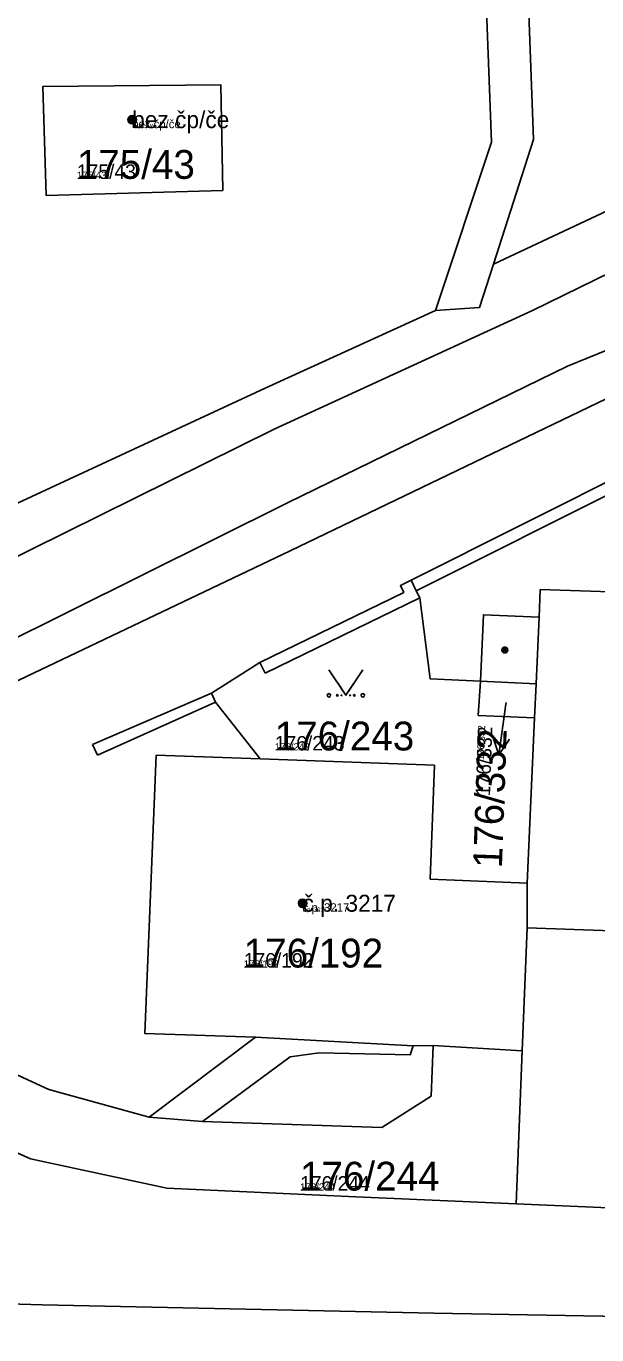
# Model space of a CAD drawing. Extents: x -759873 to -758487, y -975024 to -973516.
# Drawn here: x -759384.3 to -759350.6, y -974781.5 to -974704.3 of the extents above; entities that cross this region are included whole.
import ezdxf

# ---------------------------------------------------------------- set-up
doc = ezdxf.new("R2010")
doc.units = 0
for name, color, linetype in [('KAT_02_hranice parcel', 7, 'Continuous'), ('KAT_03_1000_st čísla parcelní', 7, 'Continuous'), ('KAT_03_1000_čísla parcelní', 7, 'Continuous'), ('KAT_03_1000_čísla popisná', 7, 'Continuous'), ('KAT_03_250_st čísla parcelní', 7, 'Continuous'), ('KAT_03_250_čísla parcelní', 7, 'Continuous'), ('KAT_03_250_čísla popisná', 7, 'Continuous'), ('KAT_03_500_st čísla parcelní', 7, 'Continuous'), ('KAT_03_500_čísla parcelní', 7, 'Continuous'), ('KAT_03_500_čísla popisná', 7, 'Continuous'), ('KAT_04_vnitřní kresba', 7, 'Continuous'), ('KAT_05_1000_značky kultur', 7, 'Continuous'), ('KAT_05_250_značky kultur', 7, 'Continuous'), ('KAT_05_500_značky kultur', 7, 'Continuous'), ('KAT_07_1000_značky budov', 7, 'Continuous'), ('KAT_07_250_značky budov', 7, 'Continuous'), ('KAT_07_500_značky budov', 7, 'Continuous'), ('KAT_12_pomocná šipka', 7, 'Continuous'), ('KAT_14_plocha_budovy', 7, 'Continuous'), ('KAT_14_plocha_pozemek', 7, 'Continuous')]:
    doc.layers.add(name, color=color, linetype=linetype)

msp = doc.modelspace()

# ---------------------------------------------------------------- linework, layer by layer
at = {"layer": 'KAT_02_hranice parcel'}
for p, q in [((-759354.3, -974745.08), (-759354.73, -974754.83)), ((-759354.74, -974757.45), (-759354.73, -974754.83)), ((-759355.03, -974764.72), (-759354.74, -974757.45)), ((-759355.03, -974764.72), (-759355.39, -974773.73))]:
    msp.add_line(p, q, dxfattribs=at)
for points in [[(-759360.14, -974721.06), (-759356.84, -974711.13), (-759357.26, -974700.21), (-759357.47, -974694.62)], [(-759318.71, -974700.17), (-759354.98, -974694.48), (-759354.76, -974700.34), (-759354.37, -974710.98), (-759356.72, -974718.32)], [(-759318.71, -974700.17), (-759321.9, -974701.95), (-759356.72, -974718.32)], [(-759372.67, -974713.98), (-759372.79, -974707.75), (-759383.27, -974707.85), (-759383.08, -974714.28), (-759372.67, -974713.98)], [(-759356.72, -974718.32), (-759357.54, -974720.88), (-759360.14, -974721.06)], [(-759338.69, -974720.79), (-759368.71, -974735.24), (-759393.08, -974746.85), (-759424.93, -974762.5)], [(-759407.29, -974742.88), (-759370.17, -974725.64), (-759360.14, -974721.06)], [(-759361.58, -974736.96), (-759348.29, -974730.29), (-759349.19, -974728.08), (-759348.55, -974727.8), (-759346.93, -974727.1), (-759346.28, -974726.82), (-759345, -974729.6), (-759333.48, -974730.01), (-759330.21, -974730.19), (-759329.89, -974726.69), (-759329.3, -974726.82)], [(-759370.47, -974747.49), (-759373.1, -974744.16), (-759373.34, -974743.62), (-759370.49, -974741.82), (-759362.01, -974737.68), (-759362.21, -974737.28), (-759361.58, -974736.96)], [(-759361.58, -974736.96), (-759361.27, -974737.59), (-759361.07, -974738), (-759360.45, -974742.78), (-759357.49, -974742.92)], [(-759323.14, -974738.53), (-759353.97, -974737.52), (-759354.04, -974739.15), (-759357.32, -974739), (-759357.49, -974742.92)], [(-759354.3, -974745.08), (-759357.62, -974744.93), (-759357.49, -974742.92)], [(-759357.49, -974742.92), (-759354.21, -974743.08), (-759354.3, -974745.08)], [(-759370.47, -974747.49), (-759376.59, -974747.27), (-759377.26, -974763.69), (-759370.74, -974763.9), (-759377.01, -974768.63)], [(-759354.73, -974754.83), (-759360.45, -974754.58), (-759360.2, -974747.87), (-759370.47, -974747.49)], [(-759354.74, -974757.45), (-759349.74, -974757.64), (-759349.83, -974759.39), (-759331.3, -974760.1), (-759331.26, -974758.35), (-759323.94, -974758.63), (-759321.81, -974758.71)], [(-759321.81, -974758.71), (-759321.95, -974763.67), (-759319.84, -974763.72), (-759319.94, -974767.65), (-759322.08, -974767.68), (-759322.29, -974775.16), (-759345.4, -974774.17), (-759355.39, -974773.73)], [(-759395.83, -974765.08), (-759394.67, -974760.92), (-759389.25, -974764.08), (-759382.92, -974767), (-759377.01, -974768.63)], [(-759424.93, -974762.5), (-759425.59, -974765.85), (-759424.23, -974769.73), (-759420.74, -974774.82), (-759416.74, -974776.65), (-759408.58, -974778.44), (-759401.14, -974779.15), (-759383.31, -974779.68), (-759360.24, -974780.18), (-759335.92, -974780.61), (-759318.75, -974781.06), (-759302.75, -974781.4)], [(-759377.01, -974768.63), (-759373.86, -974768.88), (-759368.7, -974765.06), (-759366.99, -974764.83), (-759361.64, -974764.95), (-759361.45, -974764.42), (-759360.28, -974764.39), (-759355.03, -974764.72)], [(-759355.39, -974773.73), (-759364.83, -974773.31), (-759375.96, -974772.8), (-759384.01, -974771.08), (-759388.88, -974768.9)]]:
    msp.add_lwpolyline(points, dxfattribs=at)
at = {"layer": 'KAT_03_1000_čísla popisná'}
for centre in [(-759378.01, -974709.81), (-759367.97, -974756.01)]:
    msp.add_circle(centre, 0.25, dxfattribs=at)
at = {"layer": 'KAT_03_250_čísla popisná'}
for centre in [(-759378.01, -974709.81), (-759367.97, -974756.01)]:
    msp.add_circle(centre, 0.0625, dxfattribs=at)
at = {"layer": 'KAT_03_500_čísla popisná'}
for centre in [(-759378.01, -974709.81), (-759367.97, -974756.01)]:
    msp.add_circle(centre, 0.125, dxfattribs=at)
at = {"layer": 'KAT_04_vnitřní kresba'}
for p, q in [((-759354.42, -974721.07), (-759327.47, -974707.8)), ((-759369.64, -974728.06), (-759354.42, -974721.07)), ((-759352.37, -974724.34), (-759343.54, -974720.75)), ((-759368.86, -974732.4), (-759352.37, -974724.34)), ((-759396.05, -974741.14), (-759369.64, -974728.06)), ((-759361.27, -974737.59), (-759347.98, -974730.92)), ((-759393.91, -974744.86), (-759368.86, -974732.4)), ((-759370.18, -974742.45), (-759361.07, -974738)), ((-759354.21, -974743.08), (-759354.04, -974739.15)), ((-759370.49, -974741.82), (-759370.18, -974742.45)), ((-759380.34, -974746.65), (-759373.34, -974743.62)), ((-759380.05, -974747.28), (-759373.1, -974744.16)), ((-759380.34, -974746.65), (-759380.05, -974747.28)), ((-759370.74, -974763.9), (-759361.45, -974764.42)), ((-759360.4, -974767.39), (-759360.28, -974764.39)), ((-759363.3, -974769.23), (-759360.4, -974767.39)), ((-759373.86, -974768.88), (-759363.3, -974769.23))]:
    msp.add_line(p, q, dxfattribs=at)
at = {"layer": 'KAT_05_1000_značky kultur'}
msp.add_lwpolyline([(-759366.42, -974742.249), (-759365.42, -974743.75), (-759364.42, -974742.249)], dxfattribs=at)
for centre in [(-759366.42, -974743.749), (-759364.42, -974743.749)]:
    msp.add_circle(centre, 0.1, dxfattribs=at)
at = {"layer": 'KAT_05_250_značky kultur'}
msp.add_lwpolyline([(-759365.67, -974743.375), (-759365.42, -974743.75), (-759365.17, -974743.375)], dxfattribs=at)
for centre in [(-759365.67, -974743.75), (-759365.17, -974743.75)]:
    msp.add_circle(centre, 0.025, dxfattribs=at)
at = {"layer": 'KAT_05_500_značky kultur'}
msp.add_lwpolyline([(-759365.92, -974743), (-759365.42, -974743.75), (-759364.92, -974743)], dxfattribs=at)
for centre in [(-759365.92, -974743.75), (-759364.92, -974743.75)]:
    msp.add_circle(centre, 0.05, dxfattribs=at)
at = {"layer": 'KAT_07_1000_značky budov'}
for centre in [(-759378.017, -974709.809), (-759356.057, -974741.079), (-759367.977, -974756.009)]:
    msp.add_circle(centre, 0.175, dxfattribs=at)
at = {"layer": 'KAT_07_250_značky budov'}
for centre in [(-759378.012, -974709.81), (-759356.052, -974741.08), (-759367.972, -974756.01)]:
    msp.add_circle(centre, 0.0437, dxfattribs=at)
at = {"layer": 'KAT_07_500_značky budov'}
for centre in [(-759378.013, -974709.81), (-759356.053, -974741.08), (-759367.973, -974756.01)]:
    msp.add_circle(centre, 0.0875, dxfattribs=at)
at = {"layer": 'KAT_12_pomocná šipka'}
for p, q in [((-759355.99, -974744.28), (-759356.408, -974747.252)), ((-759355.98, -974744.18), (-759355.99, -974744.28)), ((-759356.408, -974747.252), (-759356.764, -974746.19)), ((-759356.408, -974747.252), (-759355.772, -974746.33))]:
    msp.add_line(p, q, dxfattribs=at)
at = {"layer": 'KAT_14_plocha_budovy'}
for points in [[(-759383.08, -974714.28), (-759372.67, -974713.98), (-759372.79, -974707.75), (-759383.27, -974707.85)], [(-759353.97, -974737.52), (-759354.04, -974739.15), (-759354.21, -974743.08), (-759354.3, -974745.08), (-759354.73, -974754.83), (-759354.74, -974757.45), (-759349.74, -974757.64), (-759331.26, -974758.35), (-759323.94, -974758.63), (-759323.64, -974751.02), (-759323.14, -974738.53)], [(-759360.28, -974764.39), (-759355.03, -974764.72), (-759354.74, -974757.45), (-759354.73, -974754.83), (-759360.45, -974754.58), (-759360.2, -974747.87), (-759370.47, -974747.49), (-759376.59, -974747.27), (-759377.26, -974763.69), (-759370.74, -974763.9), (-759361.45, -974764.42)]]:
    msp.add_lwpolyline(points, close=True, dxfattribs=at)
at = {"layer": 'KAT_14_plocha_pozemek'}
for points in [[(-759272.2, -974639.41), (-759281.65, -974658.4), (-759285.91, -974664.61), (-759289.93, -974671.68), (-759292.94, -974676.6), (-759294.74, -974679.54), (-759302.19, -974688.3), (-759308.07, -974693.53), (-759315.75, -974698.43), (-759315.34, -974698.65), (-759317.07, -974700.43), (-759318.71, -974700.17), (-759321.9, -974701.95), (-759356.72, -974718.32), (-759357.54, -974720.88), (-759360.14, -974721.06), (-759370.17, -974725.64), (-759407.29, -974742.88), (-759417.45, -974747.54), (-759420.68, -974749.02), (-759440.41, -974758.08), (-759470.53, -974765.37)], [(-759459.82, -974776.57), (-759452, -974776.85), (-759432.32, -974766.17), (-759431.64, -974765.8), (-759424.93, -974762.5), (-759393.08, -974746.85), (-759368.71, -974735.24), (-759338.69, -974720.79), (-759334.79, -974718.9), (-759324.54, -974713.59), (-759321.22, -974711.76), (-759310.73, -974705.56), (-759302.37, -974699.71), (-759294.92, -974692.6), (-759285.8, -974680.51), (-759284.4, -974678.27), (-759283.65, -974677.06), (-759283.26, -974675.23), (-759282.29, -974673.85), (-759279.86, -974670.39), (-759274.06, -974660.4), (-759274.03, -974662.11), (-759273.99, -974664.17)], [(-759407.29, -974742.88), (-759370.17, -974725.64), (-759360.14, -974721.06), (-759356.84, -974711.13), (-759357.26, -974700.21), (-759357.47, -974694.62), (-759369.91, -974695.27), (-759381.65, -974695.89), (-759382.64, -974695.94), (-759392.71, -974696.47)], [(-759338.69, -974720.79), (-759368.71, -974735.24), (-759393.08, -974746.85)], [(-759389.25, -974764.08), (-759382.92, -974767), (-759377.01, -974768.63), (-759370.74, -974763.9), (-759377.26, -974763.69), (-759376.59, -974747.27), (-759370.47, -974747.49), (-759373.1, -974744.16), (-759373.34, -974743.62), (-759370.49, -974741.82), (-759362.01, -974737.68), (-759362.21, -974737.28), (-759361.58, -974736.96), (-759348.29, -974730.29)], [(-759348.29, -974730.29), (-759361.58, -974736.96), (-759361.27, -974737.59), (-759361.07, -974738), (-759360.45, -974742.78), (-759357.49, -974742.92), (-759357.32, -974739), (-759354.04, -974739.15), (-759353.97, -974737.52), (-759323.14, -974738.53)], [(-759293.44, -974780.74), (-759301.03, -974781.35), (-759301.24, -974780.99), (-759302.75, -974781.4), (-759318.75, -974781.06), (-759335.92, -974780.61), (-759360.24, -974780.18), (-759383.31, -974779.68), (-759401.14, -974779.15), (-759408.58, -974778.44), (-759416.74, -974776.65), (-759420.74, -974774.82), (-759424.23, -974769.73), (-759425.59, -974765.85), (-759424.93, -974762.5), (-759431.64, -974765.8), (-759432.32, -974766.17), (-759431.12, -974766.84), (-759428.57, -974769.5), (-759418.5, -974784.52)], [(-759345.4, -974774.17), (-759355.39, -974773.73), (-759364.83, -974773.31), (-759375.96, -974772.8), (-759384.01, -974771.08), (-759388.88, -974768.9)], [(-759401.14, -974779.15), (-759383.31, -974779.68), (-759360.24, -974780.18), (-759335.92, -974780.61)]]:
    msp.add_lwpolyline(points, dxfattribs=at)
for points in [[(-759357.51, -974693.16), (-759357.47, -974694.62), (-759357.26, -974700.21), (-759356.84, -974711.13), (-759360.14, -974721.06), (-759357.54, -974720.88), (-759356.72, -974718.32), (-759354.37, -974710.98), (-759354.76, -974700.34), (-759354.98, -974694.48), (-759318.71, -974700.17), (-759317.07, -974700.43), (-759315.34, -974698.65), (-759315.75, -974698.43), (-759341.17, -974684.5), (-759354.65, -974673.32), (-759358.16, -974673.5)], [(-759354.37, -974710.98), (-759356.72, -974718.32), (-759321.9, -974701.95), (-759318.71, -974700.17), (-759354.98, -974694.48), (-759354.76, -974700.34)], [(-759372.67, -974713.98), (-759383.08, -974714.28), (-759383.27, -974707.85), (-759372.79, -974707.75)], [(-759372.67, -974713.98), (-759372.79, -974707.75), (-759383.27, -974707.85), (-759383.08, -974714.28)], [(-759354.3, -974745.08), (-759357.62, -974744.93), (-759357.49, -974742.92), (-759360.45, -974742.78), (-759361.07, -974738), (-759361.27, -974737.59), (-759361.58, -974736.96), (-759362.21, -974737.28), (-759362.01, -974737.68), (-759370.49, -974741.82), (-759373.34, -974743.62), (-759373.1, -974744.16), (-759370.47, -974747.49), (-759360.2, -974747.87), (-759360.45, -974754.58), (-759354.73, -974754.83)], [(-759320.34, -974751.15), (-759323.64, -974751.02), (-759323.14, -974738.53), (-759353.97, -974737.52), (-759354.04, -974739.15), (-759357.32, -974739), (-759357.49, -974742.92), (-759354.21, -974743.08), (-759354.3, -974745.08), (-759354.73, -974754.83), (-759354.74, -974757.45), (-759349.74, -974757.64), (-759349.83, -974759.39), (-759331.3, -974760.1), (-759331.26, -974758.35), (-759323.94, -974758.63), (-759321.81, -974758.71), (-759320.64, -974758.76)], [(-759357.49, -974742.92), (-759357.62, -974744.93), (-759354.3, -974745.08), (-759354.21, -974743.08)], [(-759368.7, -974765.06), (-759366.99, -974764.83), (-759361.64, -974764.95), (-759361.45, -974764.42), (-759360.28, -974764.39), (-759355.03, -974764.72), (-759354.74, -974757.45), (-759354.73, -974754.83), (-759360.45, -974754.58), (-759360.2, -974747.87), (-759370.47, -974747.49), (-759376.59, -974747.27), (-759377.26, -974763.69), (-759370.74, -974763.9), (-759377.01, -974768.63), (-759373.86, -974768.88)], [(-759355.03, -974764.72), (-759355.39, -974773.73), (-759345.4, -974774.17), (-759322.29, -974775.16), (-759322.08, -974767.68), (-759319.94, -974767.65), (-759319.84, -974763.72), (-759321.95, -974763.67), (-759321.81, -974758.71), (-759323.94, -974758.63), (-759331.26, -974758.35), (-759331.3, -974760.1), (-759349.83, -974759.39), (-759349.74, -974757.64), (-759354.74, -974757.45)], [(-759388.88, -974768.9), (-759384.01, -974771.08), (-759375.96, -974772.8), (-759364.83, -974773.31), (-759355.39, -974773.73), (-759355.03, -974764.72), (-759360.28, -974764.39), (-759361.45, -974764.42), (-759361.64, -974764.95), (-759366.99, -974764.83), (-759368.7, -974765.06), (-759373.86, -974768.88), (-759377.01, -974768.63), (-759382.92, -974767), (-759389.25, -974764.08), (-759394.67, -974760.92), (-759395.83, -974765.08), (-759391.07, -974767.92)]]:
    msp.add_lwpolyline(points, close=True, dxfattribs=at)

# ---------------------------------------------------------------- texts
at = {"layer": 'KAT_03_1000_st čísla parcelní'}
for s, p in [('175/43', (-759381.27, -974713.299)), ('176/192', (-759371.44, -974759.799))]:
    msp.add_text(s, height=1.7, dxfattribs=at).set_placement(p)
at = {"layer": 'KAT_03_1000_čísla parcelní'}
for s, p in [('176/243', (-759369.61, -974747)), ('176/244', (-759368.12, -974772.95))]:
    msp.add_text(s, height=1.7, dxfattribs=at).set_placement(p)
msp.add_text('176/332', height=1.7, rotation=88, dxfattribs=at).set_placement((-759356.226, -974753.96))
at = {"layer": 'KAT_03_1000_čísla popisná'}
for s, p in [('bez čp/če', (-759378.01, -974710.31)), ('č.p. 3217', (-759367.97, -974756.51))]:
    msp.add_text(s, height=1, dxfattribs=at).set_placement(p)
at = {"layer": 'KAT_03_250_st čísla parcelní'}
for s, p in [('175/43', (-759381.27, -974713.299)), ('176/192', (-759371.44, -974759.799))]:
    msp.add_text(s, height=0.425, dxfattribs=at).set_placement(p)
at = {"layer": 'KAT_03_250_čísla parcelní'}
msp.add_text('176/332', height=0.425, rotation=88, dxfattribs=at).set_placement((-759357.279, -974747.577))
for s, p in [('176/243', (-759369.61, -974747)), ('176/244', (-759368.12, -974772.95))]:
    msp.add_text(s, height=0.425, dxfattribs=at).set_placement(p)
at = {"layer": 'KAT_03_250_čísla popisná'}
for s, p in [('bez čp/če', (-759378.01, -974710.31)), ('č.p. 3217', (-759367.97, -974756.51))]:
    msp.add_text(s, height=0.25, dxfattribs=at).set_placement(p)
at = {"layer": 'KAT_03_500_st čísla parcelní'}
for s, p in [('175/43', (-759381.27, -974713.299)), ('176/192', (-759371.44, -974759.799))]:
    msp.add_text(s, height=0.85, dxfattribs=at).set_placement(p)
at = {"layer": 'KAT_03_500_čísla parcelní'}
msp.add_text('176/332', height=0.85, rotation=88, dxfattribs=at).set_placement((-759356.928, -974749.705))
for s, p in [('176/243', (-759369.61, -974747)), ('176/244', (-759368.12, -974772.95))]:
    msp.add_text(s, height=0.85, dxfattribs=at).set_placement(p)
at = {"layer": 'KAT_03_500_čísla popisná'}
for s, p in [('bez čp/če', (-759378.01, -974710.31)), ('č.p. 3217', (-759367.97, -974756.51))]:
    msp.add_text(s, height=0.5, dxfattribs=at).set_placement(p)

doc.saveas('drawing.dxf')
